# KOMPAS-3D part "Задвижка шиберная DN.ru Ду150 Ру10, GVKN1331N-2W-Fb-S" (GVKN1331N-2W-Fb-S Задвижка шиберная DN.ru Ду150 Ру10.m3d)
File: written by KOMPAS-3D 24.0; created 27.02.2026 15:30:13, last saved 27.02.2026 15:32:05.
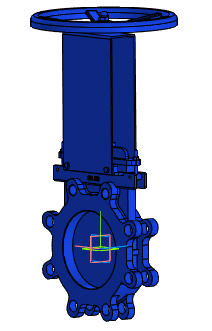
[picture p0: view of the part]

Document properties: Автор: R2D2; Полное имя файла: GVKN1331N-2W-Fb-S Задвижка шиберная DN.ru Ду150 Ру10.cdw

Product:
- Part/product: Задвижка шиберная DN.ru Ду150 Ру10  | designation GVKN1331N-2W-Fb-S
    Масса: 18
    Раздел спецификации: Прочие изделия
    Форматы листов документа: A2
    Примечание: D040-07896
    additional columns: D040-07896

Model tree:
1. Операция без истории:1

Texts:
  GVKN1331N-2W-Fb-S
